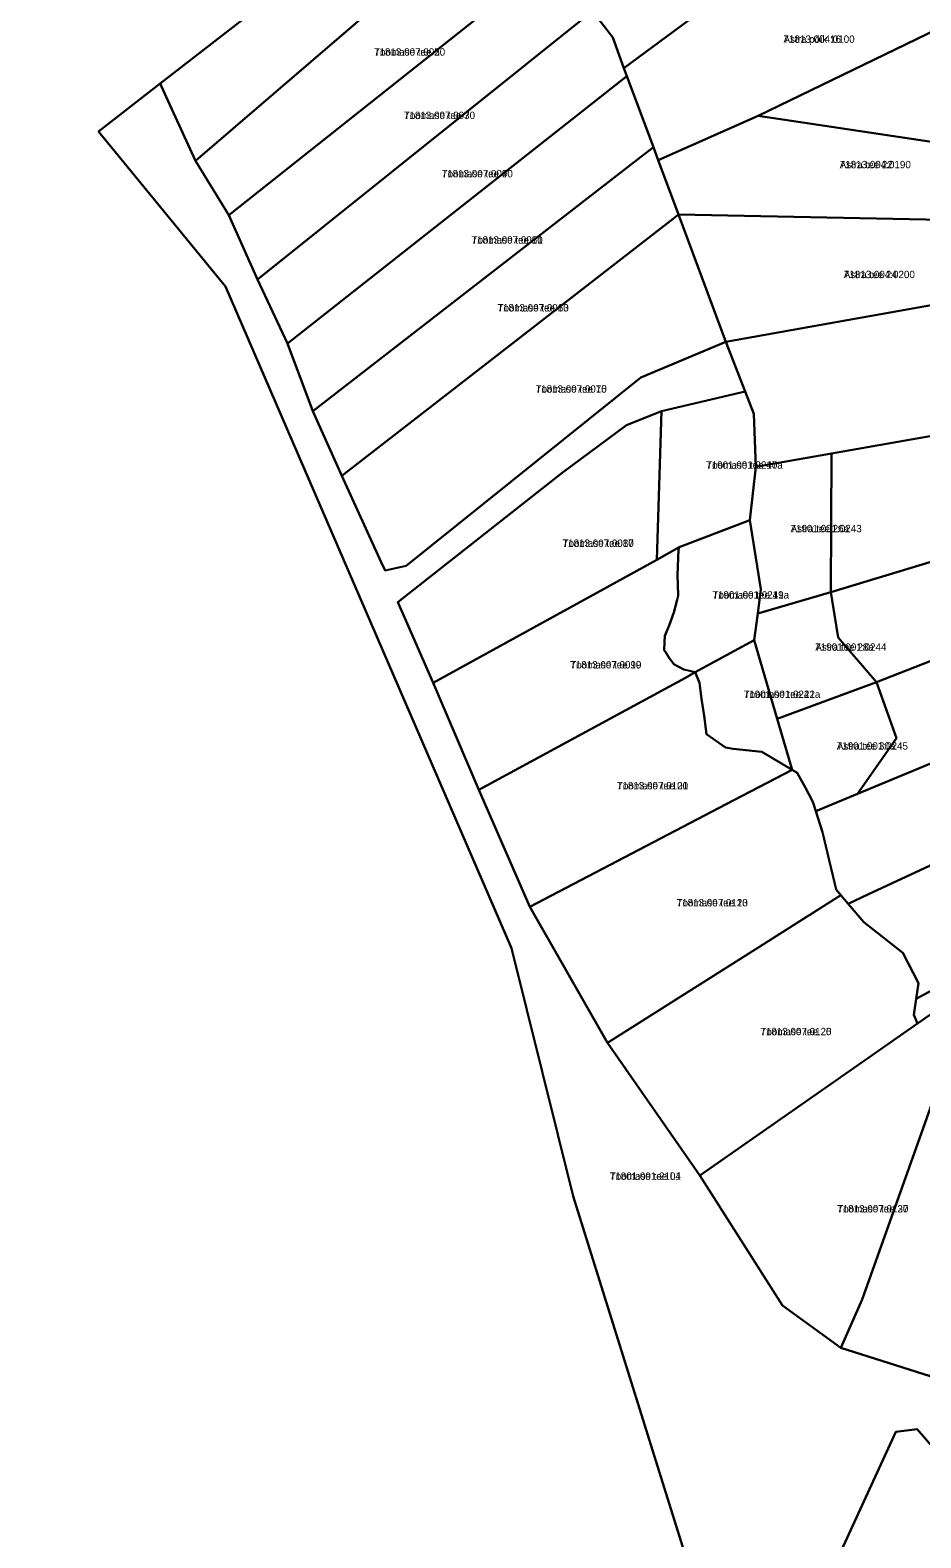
# Model space of a CAD drawing. Extents: x 529768 to 552006, y 6562269 to 6580975.
# Drawn here: x 538665.4 to 538847, y 6565221 to 6565528.2 of the extents above; entities that cross this region are included whole.
import ezdxf

# ---------------------------------------------------------------- set-up
doc = ezdxf.new("R2010")
doc.units = 0
for name, color, linetype in [('L_AADRESS', 7, 'Continuous'), ('PIIR', 7, 'Continuous'), ('TUNNUS', 7, 'Continuous')]:
    doc.layers.add(name, color=color, linetype=linetype)

msp = doc.modelspace()

# ---------------------------------------------------------------- linework, layer by layer
at = {"layer": 'PIIR'}
for points in [[(538602.83, 6565641.93), (538675.35, 6565686.57), (538676.39, 6565657.38), (538682.09, 6565620.95), (538726.52, 6565586.92), (538741.92, 6565575.01), (538754.27, 6565565.64), (538691.91, 6565517.33), (538679.35, 6565507.59), (538705.24, 6565476.02), (538763.56, 6565341.12), (538776.11, 6565290.61), (538806.23, 6565194.26)], [(538806.23, 6565194.26), (538776.11, 6565290.61), (538763.56, 6565341.12), (538705.24, 6565476.02), (538679.35, 6565507.59), (538691.91, 6565517.33), (538692.79, 6565515.4), (538699.12, 6565501.6), (538705.9, 6565490.51), (538711.77, 6565477.44), (538717.88, 6565464.39), (538723.05, 6565450.58), (538728.99, 6565437.41), (538736.98, 6565419.83), (538737.79, 6565418.08), (538742.05, 6565419.07), (538789.92, 6565457.43), (538807.23, 6565464.73), (538811.2, 6565454.6), (538794.11, 6565450.61), (538787.01, 6565447.76), (538773.89, 6565438), (538740.39, 6565411.67), (538741.14, 6565409.96), (538747.55, 6565395.25), (538756.86, 6565373.44), (538767.27, 6565349.59), (538783.14, 6565321.83), (538801.94, 6565294.85), (538818.79, 6565268.3), (538830.72, 6565259.67), (538848.92, 6565253.91)], [(538860.88, 6565447.57), (538828.76, 6565441.96), (538813.35, 6565439.24), (538812.98, 6565450.02), (538811.2, 6565454.6), (538807.23, 6565464.73), (538859.78, 6565474.07)], [(538866.07, 6565220.07), (538846.28, 6565243.14), (538841.9, 6565242.55), (538815.91, 6565185.92)]]:
    msp.add_lwpolyline(points, dxfattribs=at)
for points in [[(538786.46, 6565520.49), (538784.18, 6565526.72), (538780.05, 6565532.09), (538772.7, 6565541.58), (538817.85, 6565571.24), (538829.36, 6565553.32), (538827.91, 6565549.54), (538800.97, 6565531.23)], [(538691.91, 6565517.33), (538754.27, 6565565.64), (538759.42, 6565558.86), (538762, 6565555.58), (538699.12, 6565501.6), (538692.79, 6565515.4)], [(538699.12, 6565501.6), (538762, 6565555.58), (538771.83, 6565542.79), (538754.92, 6565529.36), (538705.9, 6565490.51)], [(538833.71, 6565540.48), (538837.8, 6565542.75), (538847.46, 6565535.72), (538854.68, 6565530.52), (538813.81, 6565510.78), (538793.43, 6565501.75), (538792.48, 6565504.4), (538787.1, 6565518.87), (538786.46, 6565520.49), (538800.97, 6565531.23), (538827.91, 6565549.54)], [(538705.9, 6565490.51), (538754.92, 6565529.36), (538771.83, 6565542.79), (538772.7, 6565541.58), (538780.05, 6565532.09), (538711.77, 6565477.44)], [(538711.77, 6565477.44), (538780.05, 6565532.09), (538784.18, 6565526.72), (538786.46, 6565520.49), (538787.1, 6565518.87), (538717.88, 6565464.39)], [(538868.19, 6565502.64), (538813.81, 6565510.78), (538854.68, 6565530.52), (538874.74, 6565515.91)], [(538717.88, 6565464.39), (538787.1, 6565518.87), (538792.48, 6565504.4), (538789.85, 6565502.36), (538723.05, 6565450.58)], [(538793.43, 6565501.75), (538813.81, 6565510.78), (538868.19, 6565502.64), (538861.46, 6565489.39), (538797.59, 6565490.65)], [(538723.05, 6565450.58), (538789.85, 6565502.36), (538792.48, 6565504.4), (538793.43, 6565501.75), (538797.59, 6565490.65), (538796.58, 6565489.86), (538728.99, 6565437.41)], [(538737.79, 6565418.08), (538736.98, 6565419.83), (538728.99, 6565437.41), (538796.58, 6565489.86), (538797.59, 6565490.65), (538807.23, 6565464.73), (538789.92, 6565457.43), (538742.05, 6565419.07)], [(538859.78, 6565474.07), (538807.23, 6565464.73), (538797.59, 6565490.65), (538861.46, 6565489.39)], [(538794.11, 6565450.61), (538811.2, 6565454.6), (538812.98, 6565450.02), (538813.35, 6565439.24), (538812.13, 6565428.38), (538797.75, 6565422.86), (538793.15, 6565420.29)], [(538741.14, 6565409.96), (538740.39, 6565411.67), (538773.89, 6565438), (538787.01, 6565447.76), (538794.11, 6565450.61), (538793.15, 6565420.29), (538747.55, 6565395.25)], [(538828.76, 6565441.96), (538860.88, 6565447.57), (538872.62, 6565427), (538828.63, 6565413.69)], [(538813.35, 6565439.24), (538828.76, 6565441.96), (538828.63, 6565413.69), (538813.74, 6565409.38), (538814.38, 6565414.3), (538812.13, 6565428.38)], [(538797.75, 6565422.86), (538812.13, 6565428.38), (538814.38, 6565414.3), (538813.74, 6565409.38), (538813.03, 6565403.9), (538801.02, 6565397.42), (538798.67, 6565397.91), (538796.67, 6565399), (538795.73, 6565400.33), (538795.03, 6565401.37), (538794.67, 6565401.9), (538794.74, 6565403.53), (538794.79, 6565404.81), (538795.73, 6565406.87), (538796.68, 6565409.53), (538797.31, 6565412.13), (538797.5, 6565412.92), (538797.44, 6565415.25), (538797.38, 6565417.16), (538797.62, 6565422.37)], [(538830.16, 6565404.46), (538828.63, 6565413.69), (538872.62, 6565427), (538880.87, 6565412.14), (538837.95, 6565395.33)], [(538747.55, 6565395.25), (538793.15, 6565420.29), (538797.75, 6565422.86), (538797.62, 6565422.37), (538797.38, 6565417.16), (538797.44, 6565415.25), (538797.5, 6565412.92), (538797.31, 6565412.13), (538796.68, 6565409.53), (538795.73, 6565406.87), (538794.79, 6565404.81), (538794.74, 6565403.53), (538794.67, 6565401.9), (538795.03, 6565401.37), (538795.73, 6565400.33), (538796.67, 6565399), (538798.67, 6565397.91), (538801.02, 6565397.42), (538799.03, 6565396.25), (538756.86, 6565373.44)], [(538813.74, 6565409.38), (538828.63, 6565413.69), (538830.16, 6565404.46), (538837.95, 6565395.33), (538817.72, 6565387.87), (538813.03, 6565403.9)], [(538842.05, 6565383.92), (538837.95, 6565395.33), (538880.87, 6565412.14), (538889.95, 6565395.78), (538834.09, 6565372.6)], [(538813.03, 6565403.9), (538817.72, 6565387.87), (538820.77, 6565377.49), (538814.56, 6565381.14), (538808.77, 6565381.75), (538807.16, 6565382.07), (538803.32, 6565384.79), (538802.82, 6565388.5), (538802.31, 6565391.97), (538801.85, 6565395.24), (538801.02, 6565397.42)], [(538820.77, 6565377.49), (538808.91, 6565371.31), (538767.27, 6565349.59), (538756.86, 6565373.44), (538799.03, 6565396.25), (538801.02, 6565397.42), (538801.85, 6565395.24), (538802.31, 6565391.97), (538802.82, 6565388.5), (538803.32, 6565384.79), (538807.16, 6565382.07), (538808.77, 6565381.75), (538814.56, 6565381.14)], [(538825.61, 6565369.09), (538825.01, 6565370.96), (538823.4, 6565373.94), (538821.78, 6565376.9), (538820.77, 6565377.49), (538817.72, 6565387.87), (538837.95, 6565395.33), (538842.05, 6565383.92), (538834.09, 6565372.6)], [(538832.18, 6565350.21), (538830.68, 6565351.97), (538829.71, 6565353.11), (538826.99, 6565364.76), (538825.61, 6565369.09), (538834.09, 6565372.6), (538889.95, 6565395.78), (538898.2, 6565380.92), (538836.18, 6565352.05)], [(538846.07, 6565330.84), (538846.56, 6565334.03), (538843.34, 6565340.22), (538835.41, 6565346.42), (538832.18, 6565350.21), (538836.18, 6565352.05), (538898.2, 6565380.92), (538909.87, 6565365.45), (538851.83, 6565333.97)], [(538767.27, 6565349.59), (538808.91, 6565371.31), (538820.77, 6565377.49), (538821.78, 6565376.9), (538823.4, 6565373.94), (538825.01, 6565370.96), (538825.61, 6565369.09), (538826.99, 6565364.76), (538829.71, 6565353.11), (538830.68, 6565351.97), (538811.91, 6565340.09), (538783.14, 6565321.83)], [(538909.87, 6565365.45), (538921.71, 6565350.12), (538872.78, 6565324.36), (538864.24, 6565320.14), (538865.7, 6565322.51), (538860.91, 6565326.59), (538857.99, 6565322.6), (538850.35, 6565328.55), (538846.35, 6565325.78), (538845.56, 6565327.58), (538846.07, 6565330.84), (538851.83, 6565333.97)], [(538801.94, 6565294.85), (538783.14, 6565321.83), (538811.91, 6565340.09), (538830.68, 6565351.97), (538832.18, 6565350.21), (538835.41, 6565346.42), (538843.34, 6565340.22), (538846.56, 6565334.03), (538846.07, 6565330.84), (538845.56, 6565327.58), (538846.35, 6565325.78)], [(538836.84, 6565319.16), (538846.35, 6565325.78), (538850.35, 6565328.55), (538857.99, 6565322.6), (538850.85, 6565312.45), (538849.57, 6565310.38), (538835.06, 6565269.56), (538830.72, 6565259.67), (538818.79, 6565268.3), (538801.94, 6565294.85)], [(538830.72, 6565259.67), (538835.06, 6565269.56), (538849.57, 6565310.38), (538850.85, 6565312.45), (538857.99, 6565322.6), (538860.91, 6565326.59), (538865.7, 6565322.51), (538864.24, 6565320.14), (538863.92, 6565316.01), (538865.4, 6565314.18), (538867.73, 6565313.26), (538869.71, 6565312.72), (538885.07, 6565307.72), (538876.27, 6565294.63), (538848.92, 6565253.91)], [(538815.91, 6565185.92), (538841.9, 6565242.55), (538846.28, 6565243.14), (538866.07, 6565220.07), (538823.59, 6565179.31)]]:
    msp.add_lwpolyline(points, close=True, dxfattribs=at)

# ---------------------------------------------------------------- texts
at = {"layer": 'L_AADRESS'}
for s, p in [('Astra põik 16', (538819.01, 6565525.65)), ('Toomase tee 5', (538735.53, 6565523.04)), ('Toomase tee 7', (538741.62, 6565510.12)), ('Toomase tee 9', (538749.32, 6565498.24)), ('Astra tee 22', (538830.47, 6565500.09)), ('Toomase tee 11', (538755.41, 6565484.73)), ('Astra tee 24', (538831.29, 6565477.69)), ('Toomase tee 13', (538760.71, 6565470.9)), ('Toomase tee 15', (538768.47, 6565454.36)), ('Toomase tee 17a', (538803.25, 6565438.86)), ('Astra tee 26a', (538820.45, 6565425.91)), ('Toomase tee 17', (538773.97, 6565422.93)), ('Toomase tee 19a', (538804.53, 6565412.39)), ('Astra tee 28a', (538825.49, 6565401.76)), ('Toomase tee 19', (538775.53, 6565398.15)), ('Toomase tee 21a', (538810.9, 6565392.14)), ('Astra tee 30a', (538829.88, 6565381.61)), ('Toomase tee 21', (538785.05, 6565373.51)), ('Toomase tee 23', (538797.22, 6565349.66)), ('Toomase tee 25', (538814.29, 6565323.41)), ('Toomase tee L1', (538783.59, 6565293.94)), ('Toomase tee 27', (538829.96, 6565287.29))]:
    msp.add_text(s, height=1.5, dxfattribs=at).set_placement(p)
at = {"layer": 'TUNNUS'}
for s, p in [('71813:004:0100', (538819.01, 6565525.65)), ('71813:007:0020', (538735.53, 6565523.04)), ('71813:007:0030', (538741.62, 6565510.12)), ('71813:007:0040', (538749.32, 6565498.24)), ('71813:004:0190', (538830.47, 6565500.09)), ('71813:007:0050', (538755.41, 6565484.73)), ('71813:004:0200', (538831.29, 6565477.69)), ('71813:007:0060', (538760.71, 6565470.9)), ('71813:007:0070', (538768.47, 6565454.36)), ('71901:001:0240', (538803.25, 6565438.86)), ('71901:001:0243', (538820.45, 6565425.91)), ('71813:007:0080', (538773.97, 6565422.93)), ('71901:001:0241', (538804.53, 6565412.39)), ('71901:001:0244', (538825.49, 6565401.76)), ('71813:007:0090', (538775.53, 6565398.15)), ('71901:001:0242', (538810.9, 6565392.14)), ('71901:001:0245', (538829.88, 6565381.61)), ('71813:007:0100', (538785.05, 6565373.51)), ('71813:007:0110', (538797.22, 6565349.66)), ('71813:007:0120', (538814.29, 6565323.41)), ('71801:001:2104', (538783.59, 6565293.94)), ('71813:007:0130', (538829.96, 6565287.29))]:
    msp.add_text(s, height=1.5, dxfattribs=at).set_placement(p)

doc.saveas('drawing.dxf')
